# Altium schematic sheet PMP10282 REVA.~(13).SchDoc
size 431 x 279 mm; Date: Not shown in title block; ApprovedBy: Not shown in title block; CheckedBy: Not shown in title block; Author: Not shown in title block; CompanyName: Not shown in title block; Engineer: Not shown in title block; Organization: Not shown in title block; Address1: Not shown in title block; Address2: Not shown in title block; Address3: Not shown in title block; Address4: Not shown in title block; DocumentNumber: 1; Revision: Use project parameter SCH_Rev; SheetNumber: 1; SheetTotal: 1; PageSetup: Record=PageOptions|CenterHorizontal=True|CenterVertical=True|PrintScale=1.00|XCorrection=1.00|YCorrection=1.00|PrintKind=0|BorderSize=5000000|LeftOffset=0|BottomOffset=0|Orientation=2|PaperLength=1000|PaperWidth=1000|Scale=100|PaperSource=15|PrintQuality=600|MediaType=1|DitherType=10|PaperKind=Letter|PrintScaleMode=1
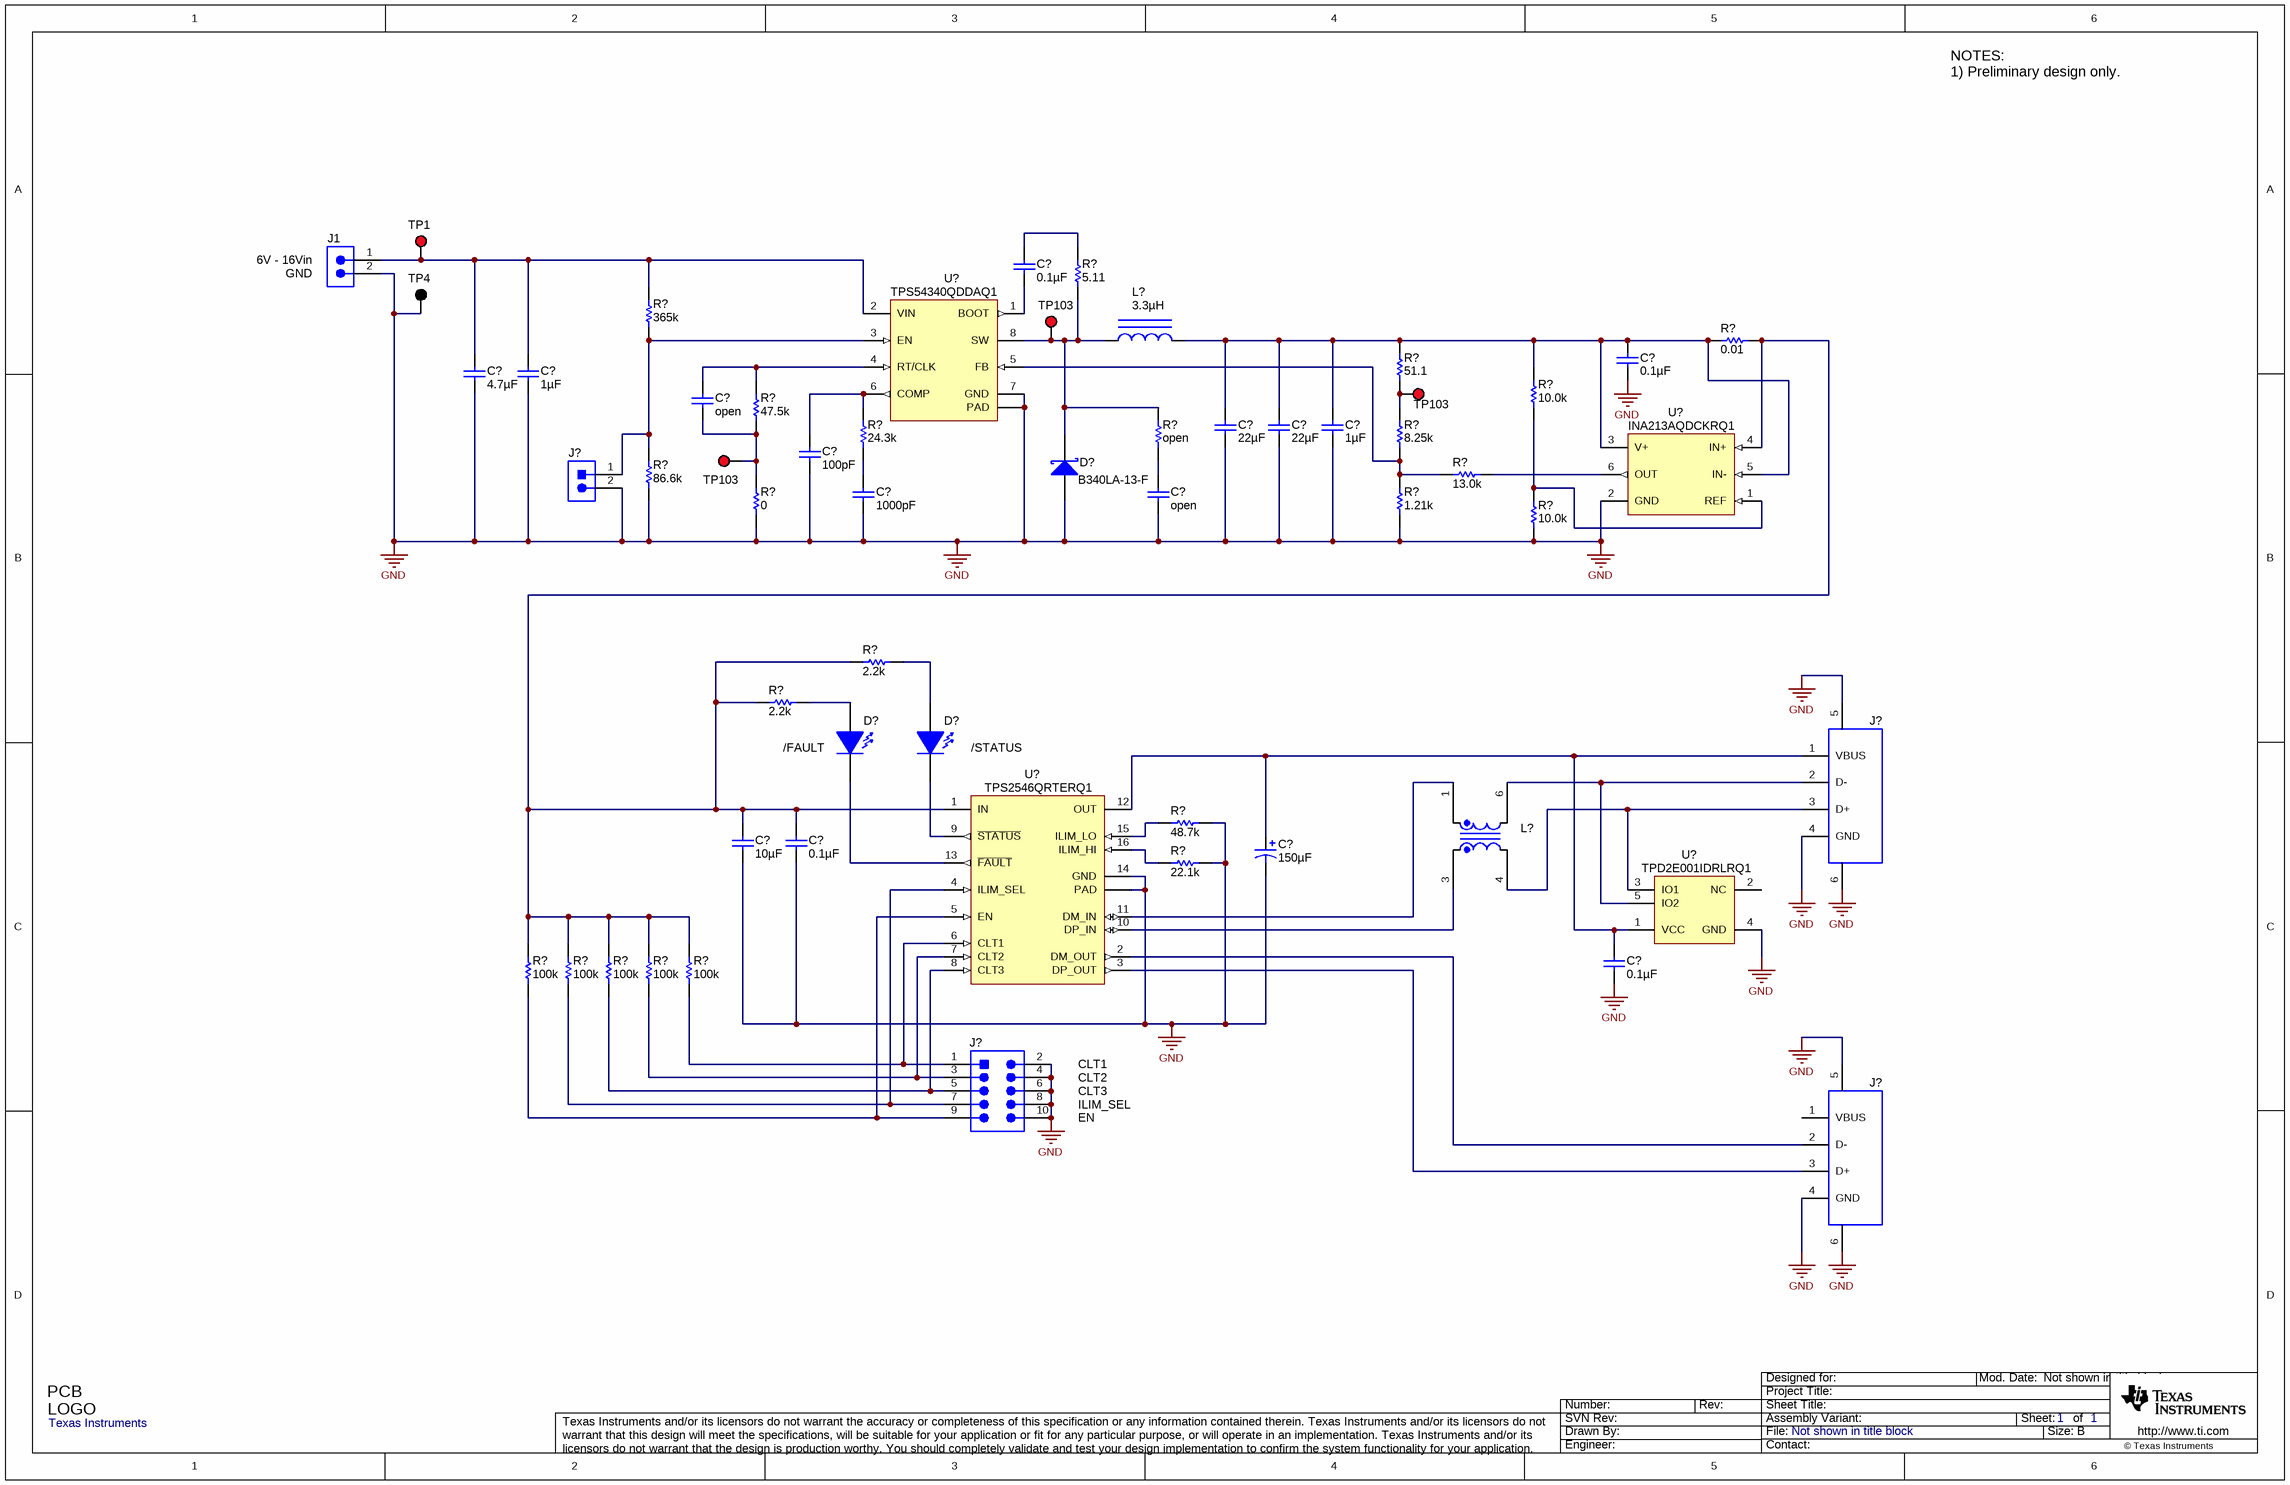
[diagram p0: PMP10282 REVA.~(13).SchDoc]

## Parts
(Parts that share a designator on the sheet are numbered #1, #2 ... from top to bottom, then left to right.)
C?#1  ValueDisplayed: 0.1µF  [0402]  (hidden comment: C1005X7R1H104K050BB)
C?#2  ValueDisplayed: 0.1µF  [0402]  (hidden comment: C1005X7R1H104K050BB)
C?#3  ValueDisplayed: 4.7µF  [1206]  (hidden comment: GRM31CR71H475KA12L)
C?#4  ValueDisplayed: 1µF  [0603]  (hidden comment: UMK107AB7105KA-T)
C?#5  ValueDisplayed: open  [0402]
C?#6  ValueDisplayed: 22µF  [0805_HV]  (hidden comment: GRM21BR61A226ME44)
C?#7  ValueDisplayed: 22µF  [0805_HV]  (hidden comment: GRM21BR61A226ME44)
C?#8  ValueDisplayed: 1µF  [0603]  (hidden comment: UMK107AB7105KA-T)
C?#9  ValueDisplayed: 100pF  [0402]  (hidden comment: GRM1535C1H101JDD5D)
C?#10  ValueDisplayed: 1000pF  [0402]  (hidden comment: C1005C0G1E102J)
C?#11  ValueDisplayed: open  [0402]
C?#12  ValueDisplayed: 10µF  [0805_HV]  (hidden comment: GRM21BR71A106KE51L)
C?#13  ValueDisplayed: 0.1µF  [0402]  (hidden comment: C1005X7R1H104K050BB)
C?#14  ValueDisplayed: 150µF  [TPB_D4]  (hidden comment: 10TPB150ML)
C?#15  ValueDisplayed: 0.1µF  [0402]  (hidden comment: C1005X7R1H104K050BB)
D?#1  B340LA-13-F  [SMA]
D?#2  value /FAULT  [LED_LTST-C190]  (hidden comment: LTST-C190GKT)
D?#3  value /STATUS  [LED_LTST-C190]  (hidden comment: LTST-C190GKT)
J1  ED555/2DS  [TERM_BLK_ED555-2DS]  (value not drawn)
J?#1  PEC02SAAN  [CONN_PEC02SAAN]  (value not drawn)
J?#2  896-43-004-00-000000  [CONN_USB_896-43-004-00-000000]  (value not drawn)
J?#3  PEC05DAAN  [CONN_PEC05DAAN]  (value not drawn)
J?#4  896-43-004-00-000000  [CONN_USB_896-43-004-00-000000]  (value not drawn)
L?#1  ValueDisplayed: 3.3µH  [SPM6530]  (hidden comment: SPM6530T-3R3M)
L?#2  985DH-1026  [NT2012]  (value not drawn)
Logo1  Texas Instruments  [TI_Stacked_Overlay_Small]  (no BOM)
R?#1  value 5.11  [0603]  (hidden comment: CRCW06035R11FKEA)
R?#2  value 365k  [0402]  (hidden comment: CRCW0402365KFKED)
R?#3  value 0.01  [2512M]  (hidden comment: ERJ-M1WSF10MU)
R?#4  value 51.1  [0402]  (hidden comment: CRCW040251R1FKED)
R?#5  value 10.0k  [0402]  (hidden comment: CRCW040210K0FKED)
R?#6  value 47.5k  [0402]  (hidden comment: CRCW040247K5FKED)
R?#7  value 24.3k  [0402]  (hidden comment: CRCW040224K3FKED)
R?#8  value open  [0805_HV]
R?#9  value 8.25k  [0402]  (hidden comment: CRCW04028K25FKED)
R?#10  value 86.6k  [0402]  (hidden comment: CRCW040286K6FKED)
R?#11  value 13.0k  [0402]  (hidden comment: CRCW040213K0FKED)
R?#12  value 0  [0402]  (hidden comment: CRCW04020000Z0ED)
R?#13  value 1.21k  [0402]  (hidden comment: CRCW04021K21FKED)
R?#14  value 10.0k  [0402]  (hidden comment: CRCW040210K0FKED)
R?#15  value 2.2k  [0402]  (hidden comment: CRCW04022K20JNED)
R?#16  value 2.2k  [0402]  (hidden comment: CRCW04022K20JNED)
R?#17  value 48.7k  [0402]  (hidden comment: CRCW040248K7FKED)
R?#18  value 22.1k  [0402]  (hidden comment: CRCW040222K1FKED)
R?#19  value 100k  [0402]  (hidden comment: CRCW0402100KFKED)
R?#20  value 100k  [0402]  (hidden comment: CRCW0402100KFKED)
R?#21  value 100k  [0402]  (hidden comment: CRCW0402100KFKED)
R?#22  value 100k  [0402]  (hidden comment: CRCW0402100KFKED)
R?#23  value 100k  [0402]  (hidden comment: CRCW0402100KFKED)
TP1  5000  [Keystone5000]  (value not drawn)
TP4  5001  [Keystone5001]  (value not drawn)
TP103#1  5010  [Keystone5010]  (value not drawn)
TP103#2  5010  [Keystone5010]  (value not drawn)
TP103#3  5010  [Keystone5010]  (value not drawn)
U?#1  TPS54340QDDAQ1  [DDA0008E_N]
U?#2  INA213AQDCKRQ1  [DCK0006A_N]
U?#3  TPD2E001IDRLRQ1  [DRL0005A]
U?#4  TPS2546QRTERQ1  [RTE0016C]

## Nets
GND: C?#2.2 C?#3.2 C?#4.2 C?#6.2 C?#7.2 C?#8.2 C?#9.2 C?#10.2 C?#11.2 C?#12.2 C?#13.2 C?#14.2(-) C?#15.2 D?#1.2(A) J1.2 J?#1.2 J?#2.4(GND) J?#2.5(Shield) J?#2.6(Shield) J?#3.2 J?#3.4 J?#3.6 J?#3.8 J?#3.10 J?#4.4(GND) J?#4.5(Shield) J?#4.6(Shield) R?#10.1 R?#12.1 R?#13.1 R?#14.1 R?#17.1 R?#18.1 TP4.1 U?#1.7(GND) U?#1.9(PAD) U?#2.2(GND) U?#3.4(GND) U?#4.14(GND) U?#4.17(PAD)
NetC?#1_1: C?#1.1 R?#1.2
NetC?#1_2: C?#1.2 U?#1.1(BOOT)
NetC?#2_1: C?#2.1 C?#6.1 C?#7.1 C?#8.1 L?#1.2 R?#3.1 R?#4.2 R?#5.2 U?#2.3(V+) U?#2.5(IN-)
NetC?#3_1: C?#3.1 C?#4.1 J1.1 R?#2.2 TP1.1 U?#1.2(VIN)
NetC?#5_1: C?#5.1 R?#6.2 U?#1.4(RT/CLK)
NetC?#5_2: C?#5.2 R?#6.1 R?#12.2 TP103#3.1
NetC?#9_1: C?#9.1 R?#7.2 U?#1.6(COMP)
NetC?#10_1: C?#10.1 R?#7.1
NetC?#11_1: C?#11.1 R?#8.1
NetC?#12_1: C?#12.1 C?#13.1 R?#3.2 R?#15.2 R?#16.2 R?#19.2 R?#20.2 R?#21.2 R?#22.2 R?#23.2 U?#2.4(IN+) U?#4.1(IN)
NetC?#14_1: C?#14.1(+) C?#15.1 J?#2.1(VBUS) U?#3.1(VCC) U?#4.12(OUT)
NetD?#1_1: D?#1.1(K) L?#1.1 R?#1.1 R?#8.2 TP103#1.1 U?#1.8(SW)
NetD?#2_1: D?#2.1(A) R?#16.1
NetD?#2_2: D?#2.2(K) U?#4.13(~{FAULT})
NetD?#3_1: D?#3.1(A) R?#15.1
NetD?#3_2: D?#3.2(K) U?#4.9(~{STATUS})
NetJ?#1_1: J?#1.1 R?#2.1 R?#10.2 U?#1.3(EN)
NetJ?#2_2: J?#2.2(D-) L?#2.6 U?#3.5(IO2)
NetJ?#2_3: J?#2.3(D+) L?#2.4 U?#3.3(IO1)
NetJ?#3_1: J?#3.1 R?#23.1 U?#4.6(CLT1)
NetJ?#3_3: J?#3.3 R?#22.1 U?#4.7(CLT2)
NetJ?#3_5: J?#3.5 R?#21.1 U?#4.8(CLT3)
NetJ?#3_7: J?#3.7 R?#20.1 U?#4.4(ILIM_SEL)
NetJ?#3_9: J?#3.9 R?#19.1 U?#4.5(EN)
NetJ?#4_2: J?#4.2(D-) U?#4.2(DM_OUT)
NetJ?#4_3: J?#4.3(D+) U?#4.3(DP_OUT)
NetL?#2_1: L?#2.1 U?#4.11(DM_IN)
NetL?#2_3: L?#2.3 U?#4.10(DP_IN)
NetR?#4_1: R?#4.1 R?#9.2 TP103#2.1
NetR?#5_1: R?#5.1 R?#14.2 U?#2.1(REF)
NetR?#9_1: R?#9.1 R?#11.2 R?#13.2 U?#1.5(FB)
NetR?#11_1: R?#11.1 U?#2.6(OUT)
NetR?#17_2: R?#17.2 U?#4.15(ILIM_LO)
NetR?#18_2: R?#18.2 U?#4.16(ILIM_HI)

Not connected (* = marked no-connect by the designer): J?#4 1(VBUS); U?#3 2(NC)

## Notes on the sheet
- NOTES:
  1) Preliminary design only.
- (near J1) 6V - 16Vin
- (near J1) GND
- CLT1
- CLT2
- CLT3
- ILIM_SEL
- EN

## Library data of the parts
C?#1 C?#2 C?#13 C?#15 = C1005X7R1H104K050BB: CAP, CERM, 0.1uF, 50V, +/-10%, X7R, 0402; Manufacturer: TDK; Polarized: N; CompType: Capacitor; U/M: EA; Cap_F: 0.0000001; Tolerance_%: 10; Value1: Unknown; VDC_V: 50; TaMin_C: -55; TaMax_C: 125
C?#3 = GRM31CR71H475KA12L: CAP, CERM, 4.7uF, 50V, +/-10%, X7R, 1206; Manufacturer: MuRata; Polarized: N; CompType: Capacitor; U/M: EA; Cap_F: 0.0000047; Tolerance_%: 10; Value1: Unknown; VDC_V: 50; TaMin_C: -55; TaMax_C: 125; Cap_Case: 2220
C?#4 C?#8 = UMK107AB7105KA-T: CAP, CERM, 1uF, 50V, +/-10%, X7R, 0603; Manufacturer: Taiyo Yuden; Polarized: N; CompType: Capacitor; U/M: EA; Cap_F: 0.000001; Tolerance_%: 10; Value1: Unknown; VDC_V: 50; TaMin_C: -55; TaMax_C: 125
C?#5 = C1005X7R1H104K050BB: CAP, open, 0402; Polarized: N; CompType: Capacitor; U/M: EA; Cap_F: 0.0000001; Tolerance_%: 10; Value1: Unknown; TaMin_C: -55; TaMax_C: 125
C?#6 C?#7 = GRM21BR61A226ME44: CAP, CERM, 22uF, 10V, +/-20%, X5R, 0805; Manufacturer: MuRata; Polarized: N; CompType: Capacitor; U/M: EA; Cap_F: 0.000022; Tolerance_%: 20; Value1: Unknown; VDC_V: 10; TaMin_C: -55; TaMax_C: 85; Cap_Case: 0805
C?#9 = GRM1535C1H101JDD5D: CAP, CERM, 100pF, 50V, +/-5%, C0G/NP0, 0402; Manufacturer: MuRata; Polarized: N; CompType: Capacitor; U/M: EA; Cap_F: 0.0000000001; Tolerance_%: 5; Value1: Unknown; VDC_V: 50; TaMin_C: -55; TaMax_C: 125
C?#10 = C1005C0G1E102J: CAP, CERM, 1000pF, 25V, +/-5%, C0G/NP0, 0402; Manufacturer: TDK; Polarized: N; CompType: Capacitor; U/M: EA; Cap_F: 0.000000001; Tolerance_%: 5; Value1: Unknown; VDC_V: 25; TaMin_C: -55; TaMax_C: 125
C?#11 = C1005C0G1E102J: CAP, open, 0402; Polarized: N; CompType: Capacitor; U/M: EA; Cap_F: 0.000000001; Tolerance_%: 5; Value1: Unknown; TempCo: C0G/NP0; TaMin_C: -55; TaMax_C: 125
C?#12 = GRM21BR71A106KE51L: CAP, CERM, 10uF, 10V, +/-10%, X7R, 0805; Manufacturer: MuRata; Polarized: N; CompType: Capacitor; U/M: EA; Cap_F: 0.00001; Tolerance_%: 10; ESR_Ohm: 0.003; Value1: 0.003 ohm; TaMin_C: -55; TaMax_C: 125; Cap_Case: 0805
C?#14 = 10TPB220M: CAP, 150uF, 10V, +/-20%, 0.04 ohm, SMD; Manufacturer: Panasonic; Polarized: Y; CompType: Capacitor; U/M: EA; Cap_F: 0.00022; Tolerance_%: 20; VDC_V: 10; ESR_Ohm: 0.04; IRMS_A: 3; TaMin_C: -55; TaMax_C: 105; Cap_Case: D
D?#1 = B340LA-13-F: Diode, Schottky, 40V, 3A, SMA; Manufacturer: Diodes Inc.; U/M: EA; Vf_V: 0.45; Value2: 0.45V; Io_A: 3; Vr_V: 40; TJmax_C: 125; RJC_CperW: 25
D?#2 D?#3 = LTST-C190GKT: LED, Green, SMD; Manufacturer: Lite-On; Vf_V: 2.1; Value2: 2.1V; Io_A: 0.02; Power_TotalModule: 0.1; Value1: 0.1W; U/M: EA
J1 = ED555/2DS: Terminal Block, 6A, 3.5mm Pitch, 2-Pos, TH; Manufacturer: On-Shore Technology, Inc.; SymbolCreator: a0412235; CompType: Connector; U/M: EA
J?#1 = PEC02SAAN: Header, 100mil, 2x1, Tin, TH; Manufacturer: Sullins Connector Solutions; SymbolCreator: a0412235; U/M: EA
J?#2 J?#4 = 896-43-004-00-000000: Connector, Receptacle, USB TYPE A, R/A, Top Mount SMT; Manufacturer: Mill-Max; SymbolCreator: a0412235; U/M: EA
J?#3 = PEC05DAAN: Header, 100mil, 5x2, Tin plated, TH; Manufacturer: Sullins Connector Solutions; SymbolCreator: a0412235; U/M: EA
L?#1 = SPM6530T-3R3M: Inductor, Shielded, Ferrite, 3.3uH, 6.8A, 0.0297 ohm, SMD; Manufacturer: TDK; Ind_H: 3.3E-6; Imax_A: 6.8; Irms: 6.8A @ 40C rise; Isat: 7.3A @ 20% inductance drop; DCR_ohm: 0.0297
L?#2 = 985DH-1023: Coupled inductor, 0.28A, 0.36 ohm, SMD; Manufacturer: Toko; SymbolCreator: a0411947; DCR_ohm: 0.21; Isat: 0.37
Logo1 = TI_Logo: Texas Instrument Corporate Signature; SymbolCreator: a0412235
R?#1 = CRCW06035R11FKEA: RES, 5.11 ohm, 1%, 0.1W, 0603; Manufacturer: Vishay-Dale; CompType: Resistor; Value_Code: 5R11; Tolerance_%: 1; Power_W: 0.1; VDC_V: 75; TempCo: 100 ppm/C; EIA_Code: E96; U/M: EA
R?#2 = CRCW0402365KFKED: RES, 365k ohm, 1%, 0.063W, 0402; Manufacturer: Vishay-Dale; CompType: Resistor; Res_ohm: 365000; Tolerance_%: 1; Power_W: 0.063; VDC_V: 50; TempCo: 100 ppm/C; EIA_Code: E96; U/M: EA
R?#3 = ERJ-M1WSF10MU: RES, 0.01 ohm, 1%, 1W, 2512; Manufacturer: Panasonic; CompType: Resistor; Value_Code: R010; Tolerance_%: 1; TempCo: 100 ppm/C; EIA_Code: E96; U/M: EA
R?#4 = CRCW040251R1FKED: RES, 51.1 ohm, 1%, 0.063W, 0402; Manufacturer: Vishay-Dale; CompType: Resistor; Value_Code: 51R1; Tolerance_%: 1; Power_W: 0.063; VDC_V: 50; TempCo: 100 ppm/C; EIA_Code: E96; U/M: EA
R?#5 R?#14 = CRCW040210K0FKED: RES, 10.0k ohm, 1%, 0.063W, 0402; Manufacturer: Vishay-Dale; CompType: Resistor; Res_ohm: 10000; Value_Code: 10k0; Tolerance_%: 1; Power_W: 0.063; VDC_V: 50; TempCo: 100 ppm/C; EIA_Code: E96; U/M: EA
R?#6 = CRCW040247K5FKED: RES, 47.5k ohm, 1%, 0.063W, 0402; Manufacturer: Vishay-Dale; CompType: Resistor; Res_ohm: 47500; Value_Code: 47k5; Tolerance_%: 1; Power_W: 0.063; VDC_V: 50; TempCo: 100 ppm/C; EIA_Code: E96; U/M: EA
R?#7 = CRCW040224K3FKED: RES, 24.3k ohm, 1%, 0.063W, 0402; Manufacturer: Vishay-Dale; CompType: Resistor; Res_ohm: 24300; Value_Code: 24k3; Tolerance_%: 1; Power_W: 0.063; VDC_V: 50; TempCo: 100 ppm/C; EIA_Code: E96; U/M: EA
R?#8 = CRCW08051K78FKEA: RES, open, 0805; CompType: Resistor; Res_ohm: 1780; Tolerance_%: 1; Power_W: 0.125; TempCo: 100 ppm/C; EIA_Code: E96; U/M: EA
R?#9 = CRCW04028K25FKED: RES, 8.25k ohm, 1%, 0.063W, 0402; Manufacturer: Vishay-Dale; CompType: Resistor; Res_ohm: 8250; Value_Code: 8k25; Tolerance_%: 1; Power_W: 0.063; VDC_V: 50; TempCo: 100 ppm/C; EIA_Code: E96; U/M: EA
R?#10 = CRCW040286K6FKED: RES, 86.6k ohm, 1%, 0.063W, 0402; Manufacturer: Vishay-Dale; CompType: Resistor; Res_ohm: 86600; Value_Code: 86k6; Tolerance_%: 1; Power_W: 0.063; VDC_V: 50; TempCo: 100 ppm/C; EIA_Code: E96; U/M: EA
R?#11 = CRCW040213K0FKED: RES, 13.0k ohm, 1%, 0.063W, 0402; Manufacturer: Vishay-Dale; CompType: Resistor; Res_ohm: 13000; Value_Code: 13k0; Tolerance_%: 1; Power_W: 0.063; VDC_V: 50; TempCo: 100 ppm/C; EIA_Code: E96; U/M: EA
R?#12 = CRCW04020000Z0ED: RES, 0 ohm, 5%, 0.063W, 0402; Manufacturer: Vishay-Dale; CompType: Resistor; Value_Code: 0000; Tolerance_%: 5; Power_W: 0.063; VDC_V: 50; TempCo: 200 ppm/C; EIA_Code: E24; U/M: EA
R?#13 = CRCW04021K21FKED: RES, 1.21k ohm, 1%, 0.063W, 0402; Manufacturer: Vishay-Dale; CompType: Resistor; Res_ohm: 1210; Value_Code: 1k21; Tolerance_%: 1; Power_W: 0.063; VDC_V: 50; TempCo: 100 ppm/C; EIA_Code: E96; U/M: EA
R?#15 R?#16 = CRCW04022K20JNED: RES, 2.2k ohm, 5%, 0.063W, 0402; Manufacturer: Vishay-Dale; CompType: Resistor; Res_ohm: 2200; Value_Code: 2k20; Tolerance_%: 5; Power_W: 0.063; VDC_V: 50; TempCo: 200 ppm/C; EIA_Code: E24; U/M: EA
R?#17 = CRCW040248K7FKED: RES, 48.7k ohm, 1%, 0.063W, 0402; Manufacturer: Vishay-Dale; CompType: Resistor; Res_ohm: 48700; Value_Code: 48k7; Tolerance_%: 1; Power_W: 0.063; VDC_V: 50; TempCo: 100 ppm/C; EIA_Code: E96; U/M: EA
R?#18 = CRCW040222K1FKED: RES, 22.1k ohm, 1%, 0.063W, 0402; Manufacturer: Vishay-Dale; CompType: Resistor; Res_ohm: 22100; Value_Code: 22k1; Tolerance_%: 1; Power_W: 0.063; VDC_V: 50; TempCo: 100 ppm/C; EIA_Code: E96; U/M: EA
R?#19-R?#23 = CRCW0402100KFKED: RES, 100k ohm, 1%, 0.063W, 0402; Manufacturer: Vishay-Dale; CompType: Resistor; Res_ohm: 100000; Tolerance_%: 1; Power_W: 0.063; VDC_V: 50; TempCo: 100 ppm/C; EIA_Code: E96; U/M: EA
TP1 = 5000: Test Point, TH, Miniature, Red; Manufacturer: Keystone; CompType: Test Point Loop; U/M: EA
TP4 = 5001: Test Point, TH, Miniature, Black; Manufacturer: Keystone; CompType: Test Point Loop; U/M: EA
TP103#1-TP103#3 = 5010: Test Point, Multipurpose, Red, TH; Manufacturer: Keystone; CompType: Test Point Loop; U/M: EA
U?#1 = TPS54340DDA: 42 V Input, 3.5 A, Step Down DC-DC Converter with Eco-mode, DDA0008E; Alternate Manufacturer: None; Manufacturer: Texas Instruments; SymbolCreator: a0411947; CompType: IC; U/M: EA
U?#2 = INA213AIDCK: Voltage Output, High or Low Side Measurement, Bi-Directional Zero-Drift Series Current-Shunt Monitor, DCK0006A; Alternate Manufacturer: None; Manufacturer: Texas Instruments; SymbolCreator: a0411947; CompType: IC; U/M: EA
U?#3 = TPD2E001IDRLRQ1: Automotive Catalog Low-Capacitance + / - 15 kV ESD-Protection Array for High-Speed Data Inter, 2 Channels, -40 to +85 degC, 5-pin SOT (DRL), Green (RoHS & no Sb/Br); Manufacturer: Texas Instruments; Alternate Manufacturer: None; Alternate PartNumber: Equivalent; Breakdown Voltage(Min)(V): 11; IEC 61000-4-2 Air-Gap(+/- kV): 15; IEC 61000-4-2 Contact(+/- kV): 8; IO Capacitance(Typ)(pF): 1.5; IO Leakage Current(nA): 1; SubFamily: ESD Solution; USB High Speed: TRUE
U?#4 = TPS2546RTE: USB Charging Port Controller and Power Switch with Load Detection, RTE0016C; Alternate Manufacturer: None; Manufacturer: Texas Instruments; SymbolCreator: a0411947; CompType: IC; U/M: EA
